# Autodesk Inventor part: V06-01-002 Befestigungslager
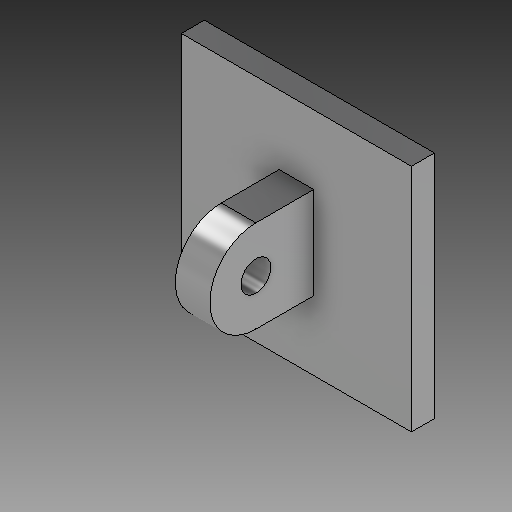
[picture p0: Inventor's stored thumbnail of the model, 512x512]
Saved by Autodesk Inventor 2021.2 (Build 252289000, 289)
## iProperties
RuleStatus: InUse
Company: R-Kon - Rodermund Konstruktion und Entwicklung GmbH
Created: 2020-09
Part Number: V06-01-002 Befestigungslager
Material: Stahl
Document SubType Name: Modeling
Designer: Felix Rodermund
Engineer: Felix Rodermund
Density: 7.85 g/cm^3
Appearance: Stahl
Mass: 7693.16 g
Surface Area: 1148.35 cm^2
Volume: 980.021 cm^3
StatusCheck: 1
Title: Teil
Author: Felix Rodermund
Revision Number: 0
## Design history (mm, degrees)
derived "V04-01-000 Gelenkarm Skelett.ipt"
  sketch "xz Befestigungslager"
    geometry: L1 (-100, 0)-(100, 0) reference; L2 (100, 0)-(100, 20) reference; L3 (100, 20)-(-100, 20) reference; L4 (-100, 20)-(-100, 0) reference; L5 (140, 0)-(-140, 0) reference; L6 (-15, 20)-(-15, 110.229) reference; L7 (-15, 110.229)-(15, 110.229) reference; L8 (15, 110.229)-(15, 20) reference; L9 (0, 110.229)-(0, 30.229) reference; L10 (-37, 345.229)-(-37, 30.229) reference; L11 (-37, 30.229)-(-17, 30.229) reference; L12 (-17, 30.229)-(-17, 113.229) reference; L13 (-17, 113.229)-(17, 113.229) reference; L14 (17, 113.229)-(17, 30.229) reference; L15 (17, 30.229)-(37, 30.229) reference; L16 (37, 30.229)-(37, 345.229) reference; L17 (0, 425.229)-(0, 345.229) reference; 6 further points
    constraints: 1 other
  sketch "yz Befestigungslager"
    geometry: L1 (40, 20)-(40, 70.229) reference; L2 (-40, 20)-(-40, 70.229) reference; L3 (0, 20)-(0, 0) reference; L4 (0, 20)-(0, 110.229) reference; L5 (100, 20)-(-100, 20) reference; L6 (-100, 20)-(-100, 0) reference; L7 (-100, 0)-(100, 0) reference; L8 (100, 0)-(100, 20) reference; L9 (-100, 0.229)-(100, 0.229) reference; A1 r 40 centre (0, 70.229) between (40, 70.229) and (-40, 70.229) reference; 2 further points
    constraints: 1 vertical alignment
  sketch "xz Gelenkdetails"
    geometry: L1 (-37, 345.229)-(-37, 30.229) reference; L2 (-37, 30.229)-(-17, 30.229) reference; L3 (-17, 30.229)-(-17, 113.229) reference; L4 (-15, 20)-(-15, 110.229) reference; L5 (-15, 110.229)-(15, 110.229) reference; L6 (15, 110.229)-(15, 20) reference; L7 (37, 30.229)-(37, 345.229) reference; L8 (47, 82.729)-(-47, 82.729) reference; L9 (-47, 82.729)-(-47, 57.729) reference; L10 (-47, 57.729)-(47, 57.729) reference; L11 (47, 57.729)-(47, 82.729) reference; L12 (-15, 57.229)-(15, 57.229) reference; L13 (47, 70.229)-(-47, 70.229) reference; 2 further points
workplane "Arbeitsebene1"
extrude "Extrusion1" new body sketch "yz Befestigungslager" stored distance "d2" = 10; taper "d3" = 0 deg
workplane "Arbeitsebene2"
extrude "Extrusion2" join sketch "yz Befestigungslager" stored distance "d4" = 10; taper "d5" = 0 deg
sketch "Skizze5"
  geometry: L1 (-15, 57.229)-(15, 57.229) reference; L2 (47, 70.229)-(-47, 70.229) reference; L3 (-15, 57.229)-(-15, 70.229); L4 (15, 57.229)-(15, 70.229); 1 further point
  constraints: 4 end point, 2 point on line, 1 parallel, 1 perpendicular
revolve "Umdrehung2" sketch "Skizze5" stored, may be unused: angle "d6" = 90 deg
node "Volumenkörper2"
